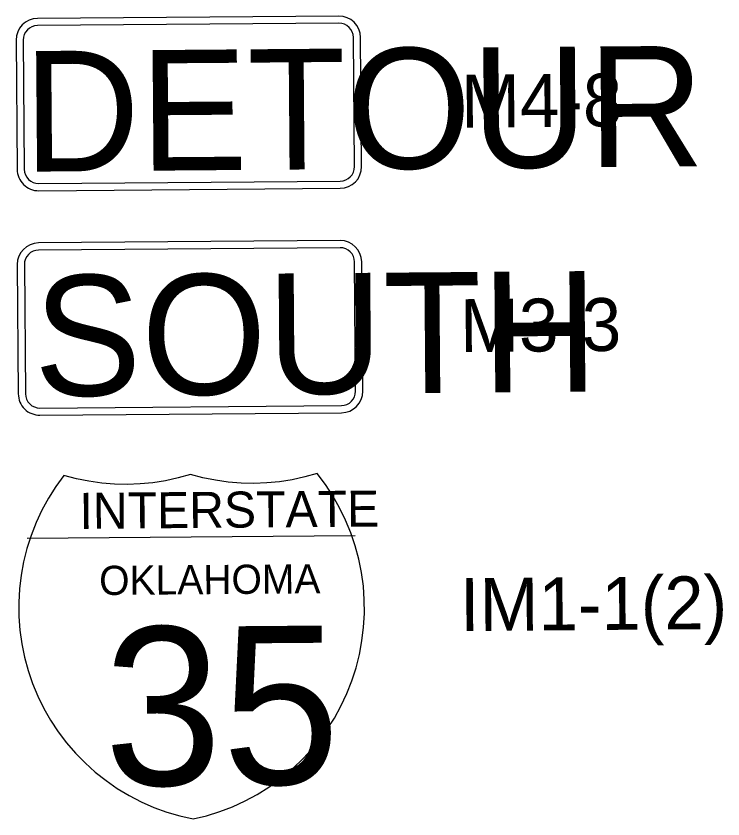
# Model space of a CAD drawing. Extents: x 2135767 to 2151731, y 141839 to 175894.
# Drawn here: x 2148998.9 to 2149079, y 145620.9 to 145712 of the extents above; entities that cross this region are included whole.
import ezdxf

# ---------------------------------------------------------------- set-up
doc = ezdxf.new("R2010")
doc.units = 0
doc.layers.add('PR_Phasing_Detour_1', color=7, linetype='Continuous')

msp = doc.modelspace()

# ---------------------------------------------------------------- linework, layer by layer
at = {"layer": 'PR_Phasing_Detour_1'}
for p, q in [((2149035.481, 145711.995), (2149001.294, 145711.72)), ((2149035.488, 145711.181), (2149001.301, 145710.906)), ((2148998.872, 145709.259), (2148998.99, 145694.607)), ((2148999.686, 145709.265), (2148999.804, 145694.613)), ((2149037.247, 145694.915), (2149037.129, 145709.566)), ((2149038.061, 145694.921), (2149037.943, 145709.573)), ((2149001.445, 145692.999), (2149035.632, 145693.274)), ((2149001.451, 145692.185), (2149035.638, 145692.46)), ((2149035.612, 145686.539), (2149001.425, 145686.264)), ((2149035.619, 145685.725), (2149001.431, 145685.45)), ((2148999.003, 145683.802), (2148999.121, 145669.151)), ((2148999.817, 145683.809), (2148999.935, 145669.157)), ((2149037.378, 145669.459), (2149037.26, 145684.11)), ((2149038.192, 145669.465), (2149038.074, 145684.117)), ((2149001.576, 145667.542), (2149035.763, 145667.818)), ((2149001.582, 145666.728), (2149035.769, 145667.004)), ((2149000.132, 145652.794), (2149037.322, 145653.093))]:
    msp.add_line(p, q, dxfattribs=at)
msp.add_lwpolyline([(2149004.304, 145659.895), (2149003.389, 145658.635), (2149002.556, 145657.32), (2149001.808, 145655.954), (2149001.149, 145654.543), (2149000.582, 145653.094), (2149000.107, 145651.611), (2148999.729, 145650.1), (2148999.447, 145648.569), (2148999.263, 145647.023), (2148999.179, 145645.468), (2148999.193, 145643.911), (2148999.307, 145642.358), (2148999.52, 145640.816), (2148999.83, 145639.29), (2149000.237, 145637.787), (2149000.739, 145636.313), (2149001.334, 145634.874), (2149002.019, 145633.476), (2149002.792, 145632.125), (2149003.65, 145630.825), (2149004.588, 145629.583), (2149005.604, 145628.403), (2149006.693, 145627.29), (2149007.851, 145626.249), (2149009.073, 145625.284), (2149010.354, 145624.398), (2149011.688, 145623.596), (2149013.071, 145622.881), (2149014.497, 145622.255), (2149015.96, 145621.722), (2149017.453, 145621.283), (2149018.972, 145620.939), (2149020.485, 145621.307), (2149021.972, 145621.77), (2149023.426, 145622.327), (2149024.841, 145622.976), (2149026.213, 145623.713), (2149027.534, 145624.537), (2149028.8, 145625.443), (2149030.006, 145626.427), (2149031.147, 145627.487), (2149032.218, 145628.617), (2149033.215, 145629.813), (2149034.134, 145631.071), (2149034.97, 145632.384), (2149035.721, 145633.748), (2149036.384, 145635.156), (2149036.956, 145636.605), (2149037.434, 145638.087), (2149037.817, 145639.596), (2149038.102, 145641.126), (2149038.29, 145642.672), (2149038.379, 145644.227), (2149038.368, 145645.784), (2149038.259, 145647.337), (2149038.05, 145648.88), (2149037.744, 145650.406), (2149037.341, 145651.91), (2149036.843, 145653.386), (2149036.252, 145654.826), (2149035.57, 145656.226), (2149034.801, 145657.58), (2149033.947, 145658.881), (2149033.012, 145660.126), (2149031.61, 145659.728), (2149030.188, 145659.415), (2149028.749, 145659.187), (2149027.299, 145659.045), (2149025.843, 145658.99), (2149024.387, 145659.022), (2149022.935, 145659.14), (2149021.493, 145659.345), (2149020.065, 145659.636), (2149018.658, 145660.011), (2149017.256, 145659.613), (2149015.834, 145659.299), (2149014.395, 145659.071), (2149012.945, 145658.93), (2149011.49, 145658.874), (2149010.033, 145658.906), (2149008.581, 145659.025), (2149007.139, 145659.229), (2149005.712, 145659.52), (2149004.304, 145659.895)], dxfattribs=at)
for centre, radius, start, end in [((2149001.314, 145709.278), 2.442, 90.46107, 180.46107), ((2149035.501, 145709.553), 2.442, 0.46107, 90.46107), ((2149001.314, 145709.278), 1.628, 90.46107, 180.46107), ((2149035.501, 145709.553), 1.628, 0.46107, 90.46107), ((2149001.432, 145694.627), 2.442, 180.46107, 270.46107), ((2149001.432, 145694.627), 1.628, 180.46107, 270.46107), ((2149035.619, 145694.902), 1.628, 270.46107, 0.46107), ((2149035.619, 145694.902), 2.442, 270.46107, 0.46107), ((2149001.445, 145683.822), 2.442, 90.46107, 180.46107), ((2149035.632, 145684.097), 2.442, 0.46107, 90.46107), ((2149001.445, 145683.822), 1.628, 90.46107, 180.46107), ((2149035.632, 145684.097), 1.628, 0.46107, 90.46107), ((2149001.562, 145669.17), 2.442, 180.46107, 270.46107), ((2149001.562, 145669.17), 1.628, 180.46107, 270.46107), ((2149035.75, 145669.446), 1.628, 270.46107, 0.46107), ((2149035.75, 145669.446), 2.442, 270.46107, 0.46107)]:
    msp.add_arc(centre, radius, start, end, dxfattribs=at)

# ---------------------------------------------------------------- texts
for s, height, p in [('DETOUR', 13.6754, (2148999.758, 145694.342)), ('M4-8', 6, (2149049.361, 145699.339)), ('SOUTH', 13.6754, (2149000.928, 145668.894)), ('M3-3', 6, (2149049.243, 145673.88)), ('INTERSTATE', 4.0845, (2149006.077, 145653.833)), ('OKLAHOMA', 3.3102, (2149008.309, 145646.331)), ('IM1-1(2)', 6, (2149049.23, 145642.242)), ('35', 17.9738, (2149008.901, 145624.699))]:
    msp.add_text(s, height=height, rotation=0.46107, dxfattribs=at).set_placement(p)

doc.saveas('drawing.dxf')
